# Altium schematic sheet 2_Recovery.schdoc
size 309 x 223 mm; Symbol: Sheet-Symbol_A4; Device: Sheet-Symbol_A4; Company: EasyEDA.com; Drawed: EasyEDA Pro; Reviewed: EasyEDA Pro; Version: V0.1; Page Size: A4; @Project Name: Recovery-Board-Kaveet-Saksham-Edition; @Page Count: 3; @Update Date: 2023-09-14; @Create Date: 2023-08-02; @Schematic Name: Schematic; Part Number: JLCPCB-002; @Page No: 2; @Page Name: Recovery
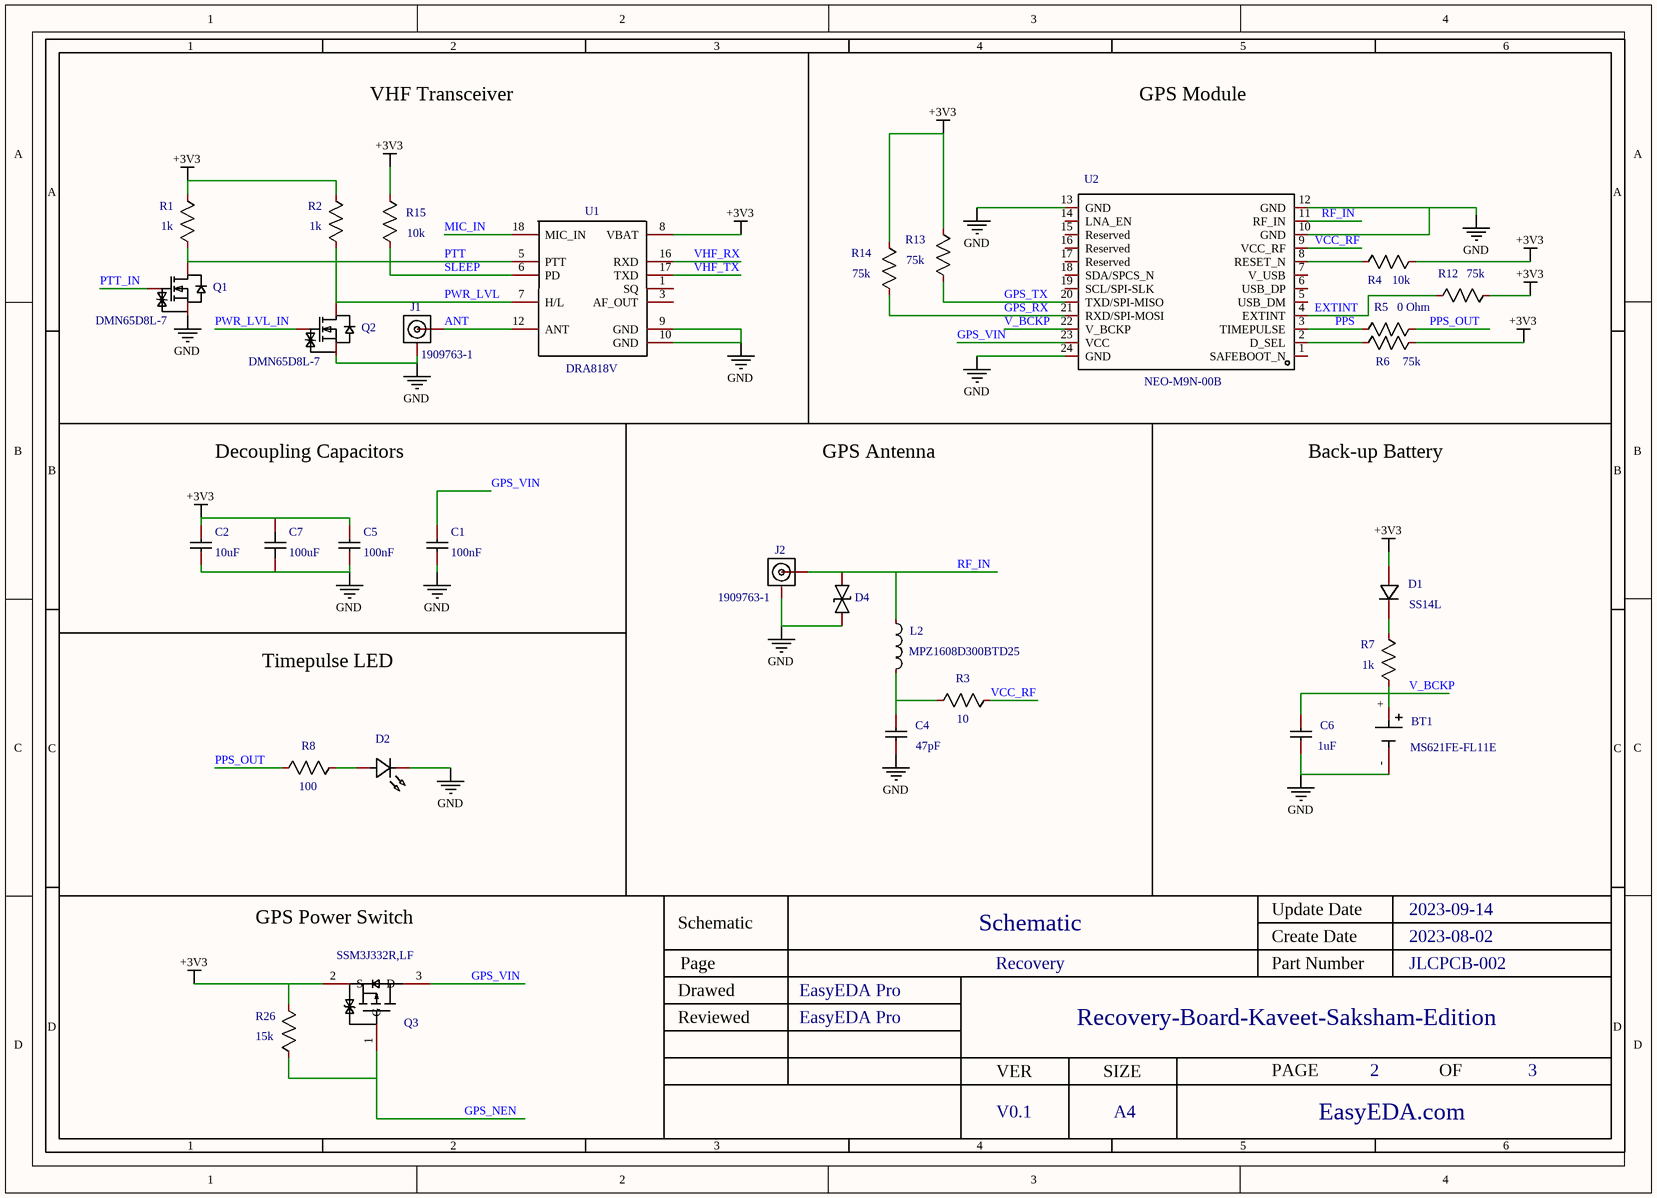
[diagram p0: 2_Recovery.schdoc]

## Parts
BT1  MS621FE-FL11E
C1  100nF
C2  10uF
C4  47pF
C5  100nF
C6  1uF
C7  100uF
D1  SS14L
D2  16-213/BHC-ZL1M2B6Y/3T  (value not drawn)
D4  LESD3Z5.0CMT1G  (value not drawn)
J1  1909763-1
J2  1909763-1
L2  MPZ1608D300BTD25
Q1  DMN65D8L-7
Q2  DMN65D8L-7
Q3  SSM3J332R,LF  [SOT-23F_L2.9-W1.8-P0.95-LS2.4-BR]
R1  1k
R2  1k
R3  10
R4  10k
R5  0 Ohm
R6  75k
R7  1k
R8  100
R12  75k
R13  75k
R14  75k
R15  10k
R26  15k
U1  DRA818V
U2  NEO-M9N-00B

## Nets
+3V3: C2.2 C5.2 C7.1 D1.2(A) Q3.2(S) R1.2 R2.2 R4.2 R6.2 R12.2 R13.2 R14.2 R15.2 R26.2 U1.8(VBAT)
GND: BT1.- C1.1 C2.1 C4.1 C5.1 C6.1 C7.2 D2.1(K) D4.1 J1.2 J2.2 Q1.2(S) Q2.2(S) U1.9(GND) U1.10(GND) U2.10(GND) U2.12(GND) U2.13(GND) U2.24(GND)
ANT: J1.1 U1.12(ANT)
EXTINT: R12.1 U2.4(EXTINT)
GPS_NEN: Q3.1(G) R26.1
GPS_RX: R14.1 U2.21(RXD/SPI-MOSI)
GPS_TX: R13.1 U2.20(TXD/SPI-MISO)
GPS_VIN: C1.2 Q3.3(D) U2.23(VCC)
MIC_IN: U1.18(MIC_IN)
PPS: R5.1 U2.3(TIMEPULSE)
PPS_OUT: R5.2 R8.1
PTT: Q1.3(D) R1.1 U1.5(PTT)
PTT_IN: Q1.1(G)
PWR_LVL: Q2.3(D) R2.1 U1.7(H/L)
PWR_LVL_IN: Q2.1(G)
RF_IN: D4.2 J2.1 L2.1 U2.11(RF_IN)
SLEEP: R15.1 U1.6(PD)
V_BCKP: BT1.+ C6.2 R7.1 U2.22(V_BCKP)
VCC_RF: R3.2 U2.9(VCC_RF)
VHF_RX: U1.16(RXD)
VHF_TX: U1.17(TXD)
NetC4_2: C4.2 L2.2 R3.1
NetD1_1: D1.1(C) R7.2
NetD2_2: D2.2(A) R8.2
NetR4_1: R4.1 U2.8(RESET_N)
NetR6_1: R6.1 U2.2(D_SEL)

Not connected (* = marked no-connect by the designer): U1 1(SQ) 3(AF_OUT); U2 1(SAFEBOOT_N) 5(USB_DM) 6(USB_DP) 7(V_USB) 14(LNA_EN) 15(Reserved) 16(Reserved) 17(Reserved) 18(SDA/SPCS_N) 19(SCL/SPI-SLK)

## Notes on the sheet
- VHF Transceiver
- GPS Module
- Decoupling Capacitors
- GPS Antenna
- Back-up Battery
- Timepulse LED
- GPS Power Switch

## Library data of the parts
BT1 = MS621FE-FL11E: Convert to PCB: yes; Origin Footprint: BAT_MS621FE-FL11E
C1 C5 = CC0402ZRY5V7BB104: Manufacturer: YAGEO(国巨); Convert to PCB: yes; Origin Footprint: C0402
C2 = GRM188R60G106ME47D: Manufacturer: muRata(村田); Convert to PCB: yes; Origin Footprint: C0603; Check: true
C4 = GRM1555C1H470JA01D: Manufacturer: muRata(村田); Convert to PCB: yes; Origin Footprint: C0402
C6 = GRM155R61E105KA12D: Manufacturer: muRata(村田); Convert to PCB: yes; Origin Footprint: C0402
C7 = GRM32ER60J107ME20L: Manufacturer: muRata(村田); Convert to PCB: yes; Origin Footprint: C1210
D1 = SS14L_R1_00001: Manufacturer: PANJIT(强茂); Convert to PCB: yes; Origin Footprint: SMA_L4.4-W2.6-LS5.0-RD
D2 = 16-213/BHC-ZL1M2B6Y/3T: Manufacturer: EVERLIGHT(亿光); Convert to PCB: yes; Origin Footprint: LED0402-RD_BLUE
D4 = LESD3Z5.0CMT1G: Manufacturer: LRC(乐山无线电); Convert to PCB: yes; Origin Footprint: SOD-323_L1.8-W1.3-LS2.5-BI
J1 J2 = 1909763-1: Manufacturer: TEConnectivity(美国泰科); Convert to PCB: yes; Origin Footprint: ANT-SMD_1909763-1
L2 = MPZ1608D300BTD25: Manufacturer: TDK; Convert to PCB: yes; Origin Footprint: L0603
Q1 Q2 = DMN65D8L-7: Manufacturer: DIODES(美台); Convert to PCB: yes; Origin Footprint: SOT-23-3_L3.0-W1.7-P0.95-LS2.9-BR
Q3 = SSM3J332R,LF: Manufacturer: TOSHIBA; Add into BOM: yes
R1 R2 R7 = 1k: Convert to PCB: yes; Origin Footprint: R0603
R3 = RC0603FR-0710RL: Convert to PCB: yes; Origin Footprint: R0603
R4 R15 = RC0603FR-0710KL: Convert to PCB: yes; Origin Footprint: R0603
R5 = 0603WAF0000T5E: Convert to PCB: yes; Origin Footprint: R0603
R6 R12-R14 = RC0603FR-0775KL: Convert to PCB: yes; Origin Footprint: R0603
R8 = RC0603FR-07100RL: Convert to PCB: yes; Origin Footprint: R0603
R26 = RC0603FR-0710RL: Manufacturer Part: 0402WGF1502TCE; Symbol: 10; Convert to PCB: yes
U1 = DRA818V: Convert to PCB: yes; Origin Footprint: DORJI_DRA818V
U2 = NEO-M9N-00B: Manufacturer: null; Convert to PCB: yes; Origin Footprint: GPSM-SMD_24P-L16.0-W12.2-P1.10-BL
